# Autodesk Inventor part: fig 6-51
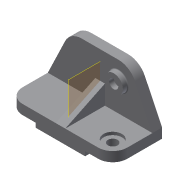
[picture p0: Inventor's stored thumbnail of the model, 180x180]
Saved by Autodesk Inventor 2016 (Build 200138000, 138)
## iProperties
Shininess: 77.0
Length Units: 11269
Angle Units: 11279
Time Units: 11290
Mass Units: 11283
Length Display Precision: 3
Angle Display Precision: 2
Created: 2001-12
Part Number: fig 6-51
Document SubType Name: Modeling
Designer: Renu Muthoo
Density: 1 g/cm^3
Material: Generic
Appearance: Default
Density: 0.0
Volumn: 0.0
Area: 0.0
PropertySet Name: Model Information
Control State: 0
Master: False
Checked Out: False
Author: Renu Muthoo
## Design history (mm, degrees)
node "Sketch1"
sketch "Sketch2"
  geometry: L1 (-67.219, 19.116)-(148.781, 19.116); L2 (148.781, 19.116)-(148.781, -0.884); L3 (-67.219, -0.884)-(-67.219, 19.116); L4 (-10.219, -0.884)-(-10.219, -9.884); L5 (-10.219, -9.884)-(91.781, -9.884); L6 (91.781, -9.884)-(91.781, -0.884); L7 (148.781, -0.884)-(91.781, -0.884); L8 (-10.219, -0.884)-(-67.219, -0.884)
  constraints: 16 end point, 5 parallel, 4 perpendicular, 2 equal length, 1 horizontal
  dimensions: "d0" = 102 distance of L4.end L5.end; "d1" = 57 distance of L4.start L3.start; "d2" = 29 distance between parallel lines of L1 L5; "d3" = 20 distance of L1.end L2.end
extrude "Extrusion1" new body sketch "Sketch2" distance "d4" = 102; taper "d5" = 0 deg
sketch "Sketch3"
  geometry: L1 (67.219, -19.116)-(-148.781, -19.116) reference; L2 (67.219, -19.116)-(31.475, -93.564); L3 (-2.781, -115.116)-(-78.781, -115.116); L4 (-113.038, -93.564)-(-148.781, -19.116); A1 r 38 centre (-2.781, -77.116) between (-2.781, -115.116) and (31.475, -93.564); A2 r 38 centre (-78.781, -77.116) between (-113.038, -93.564) and (-78.781, -115.116)
  constraints: 6 end point, 4 point on circle, 4 tangent, 2 centre point, 1 equal length, 1 equal radius, 1 parallel
  dimensions: "d6" = 96 distance between parallel lines of L3 L1; "d7" = 38 radius of A1; "d8" = 76 distance of A2.centre A1.centre
extrude "Extrusion2" join sketch "Sketch3" distance "d9" = 20; taper "d10" = 0 deg
fillet "Fillet1" dims "d11" = 30
workplane "Work Plane1"
sketch "Sketch5"
  geometry: A1 r 30 centre (-30, 0) between (-30, -30) and (0, 0) reference; 1 further point
  constraints: 1 coincident
hole "Hole1" sketch "Sketch5" at (-30, 0) diameter "d16" = 20; stored, may be unused: countersink angle "d20" = 82 deg, drill point angle "d22" = 118 deg; dims "d17" = 6, "d18" = 38, "d19" = 6, "d21" = 8
sketch "Sketch6"
  geometry: C1 r 19 at (-2.781, 77.116); C2 r 9.5 at (-2.781, 77.116); A1 r 38 centre (-2.781, 77.116) between (31.475, 93.564) and (-2.781, 115.116) reference
  constraints: 2 centre point, 2 coincident
  dimensions: "d23" = 38 diameter of C1; "d24" = 19 diameter of C2
extrude "Extrusion3" join sketch "Sketch6" distance "d25" = 10; taper "d26" = 0 deg
sketch "Sketch7"
  geometry: L1 (0, -82)-(-39.557, 0); L2 (0, -82)-(20, -82) reference; L3 (29, 22.405)-(29, -82); L4 (29, -82)-(0, -82); L5 (0, -82)-(0, 0); L6 (0, 0)-(-90.034, 0); L7 (-90.034, 0)-(-90.034, 22.405); L8 (-90.034, 22.405)-(29, 22.405); L9 (0, 0)-(-74.447, 0) reference
  constraints: 14 end point, 1 collinear, 1 point on line
feature "Rib3" sketch "Sketch7" dims "d35" = 10, "d36" = 20
fillet "Fillet3" dims "d37" = 2
body "Solid1"
other parameters: "d12" = -108
